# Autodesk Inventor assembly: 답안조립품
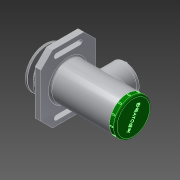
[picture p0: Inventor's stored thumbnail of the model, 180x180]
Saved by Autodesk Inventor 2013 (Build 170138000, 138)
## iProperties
Created: 2017-10
Part Number: 답안조립품
Document SubType Name: Assembly
Designer: Administrator
Author: Administrator
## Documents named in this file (20)
- C:\Users\Administrator\Desktop\471008V1021\답안조립품.iam
- C:\Users\Administrator\Desktop\471008V1021\V-벨트풀리.ipt
- C:\Users\Administrator\Desktop\471008V1021\너트 M10.ipt
- C:\Users\Administrator\Desktop\471008V1021\멈춤링 15 x 1.ipt
- C:\Users\Administrator\Desktop\471008V1021\멈춤링 35x1.6.ipt
- C:\Users\Administrator\Desktop\471008V1021\베어링 15 x 35 x 11.ipt
- C:\Users\Administrator\Desktop\471008V1021\본체.ipt
- C:\Users\Administrator\Desktop\471008V1021\볼트 M4 x 10.ipt
- C:\Users\Administrator\Desktop\471008V1021\부시1.ipt
- C:\Users\Administrator\Desktop\471008V1021\부시2.ipt
- C:\Users\Administrator\Desktop\471008V1021\사이드 커버.ipt
- 사이드 커버.ipt
- C:\Users\Administrator\Desktop\471008V1021\십자볼트 M3 x 10.ipt
- C:\Users\Administrator\Desktop\471008V1021\오일 실 15 25 7.ipt
- C:\Users\Administrator\Desktop\471008V1021\와셔 3x6.ipt
- C:\Users\Administrator\Desktop\471008V1021\와셔 4x16.ipt
- C:\Users\Administrator\Desktop\471008V1021\와셔 10x21.ipt
- C:\Users\Administrator\Desktop\471008V1021\축.ipt
- C:\Users\Administrator\Desktop\471008V1021\키 4 x 4 x 18.ipt
- C:\Users\Administrator\Desktop\471008V1021\탑 커버.ipt
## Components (2 placed, 2 different names)
1. V-벨트풀리:1
2. ISO 4017 M4 x 10:1
